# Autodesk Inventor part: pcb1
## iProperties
Shininess: 64.0
Length Units: 11269
Angle Units: 11279
Time Units: 11290
Mass Units: 11283
Length Display Precision: 3
Angle Display Precision: 2
Compacted: True
Part Number: pcb1
Document SubType Name: Modeling
Created: 2003-06
Designer: John Blackburn
Density: 0.0
Volumn: 0.0
Area: 0.0
PropertySet Name: Model Information
Control State: 0
Master: False
Checked Out: False
Author: John Blackburn
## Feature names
1. Extrusion1
2. Hole1
